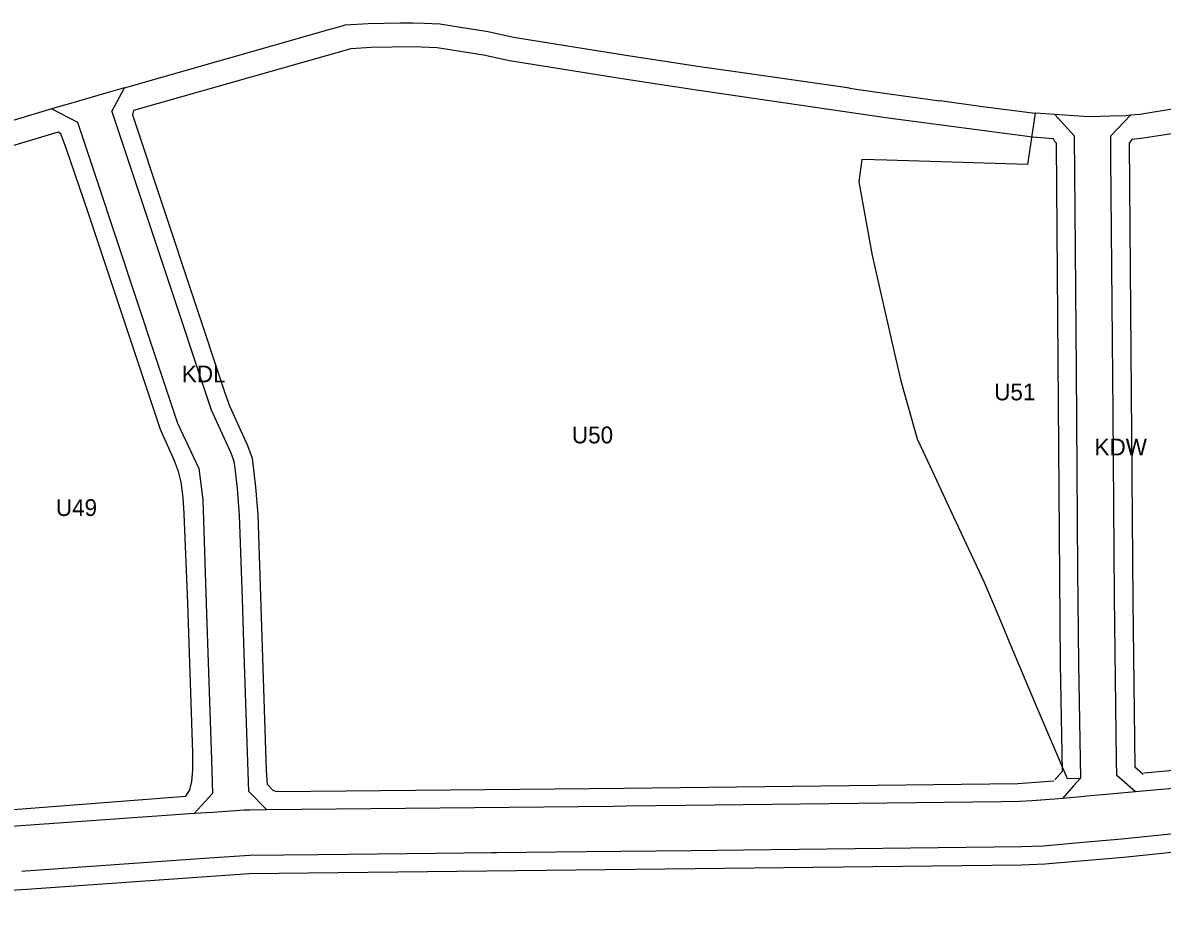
# Model space of a CAD drawing. Extents: x 7428080 to 7432143, y 5545880 to 5549217.
# Drawn here: x 7429638.6 to 7430015.1, y 5547123.1 to 5547416.2 of the extents above; entities that cross this region are included whole.
import ezdxf

# ---------------------------------------------------------------- set-up
doc = ezdxf.new("R2010")
doc.units = 0
for name, color, linetype in [('CZ_L_linie rozgraniczające tereny o różnym przeznaczeniu oraz różnych warunkach ich zabudowy i zagospodarowania', 7, 'Continuous'), ('CZ_L_maksymalne nieprzekraczalne linie zabudowy', 7, 'Continuous'), ('CZ_L_opisy_linie rozgraniczające tereny o różnym przeznaczeniu oraz różnych warunkach ich zabudowy i zagospodarowania', 7, 'Continuous')]:
    doc.layers.add(name, color=color, linetype=linetype)

msp = doc.modelspace()

# ---------------------------------------------------------------- linework, layer by layer
at = {"layer": 'CZ_L_linie rozgraniczające tereny o różnym przeznaczeniu oraz różnych warunkach ich zabudowy i zagospodarowania'}
for p, q in [((7429740.89, 5547414.25), (7429743.8, 5547415.09)), ((7429743.8, 5547415.09), (7429745.11, 5547415.46)), ((7429745.11, 5547415.46), (7429752.68, 5547415.97)), ((7429752.68, 5547415.97), (7429763.33, 5547416.12)), ((7429763.33, 5547416.12), (7429767.47, 5547416.17)), ((7429767.47, 5547416.17), (7429771.35, 5547416.03)), ((7429771.35, 5547416.03), (7429776.37, 5547415.86)), ((7429776.37, 5547415.86), (7429783.18, 5547414.68)), ((7429783.18, 5547414.68), (7429792.42, 5547413.31)), ((7429672.25, 5547394.63), (7429740.89, 5547414.25)), ((7429792.42, 5547413.31), (7429800.73, 5547411.46)), ((7429800.73, 5547411.46), (7429837.89, 5547405.52)), ((7429837.89, 5547405.52), (7429862.35, 5547401.77)), ((7429862.35, 5547401.77), (7429874.06, 5547400.11)), ((7429874.06, 5547400.11), (7429874.06, 5547400.07)), ((7429874.06, 5547400.07), (7429887.98, 5547398.04)), ((7429887.98, 5547398.04), (7429908.01, 5547395.18)), ((7429666.07, 5547392.86), (7429654.4, 5547389.52)), ((7429672.25, 5547394.63), (7429666.07, 5547392.86)), ((7429668.08, 5547387.08), (7429672.25, 5547394.63)), ((7429908.01, 5547395.18), (7429911.79, 5547394.64)), ((7429911.79, 5547394.64), (7429911.78, 5547394.6)), ((7429911.78, 5547394.6), (7429917.02, 5547393.83)), ((7429917.02, 5547393.83), (7429925.63, 5547392.57)), ((7429925.63, 5547392.57), (7429925.63, 5547392.55)), ((7429925.63, 5547392.55), (7429941.57, 5547390.39)), ((7429651.16, 5547388.59), (7429648.15, 5547387.7)), ((7429654.4, 5547389.52), (7429651.16, 5547388.59)), ((7429941.57, 5547390.39), (7429941.69, 5547390.5)), ((7429941.69, 5547390.5), (7429955.68, 5547388.51)), ((7429955.68, 5547388.51), (7429973.08, 5547386.29)), ((7429648.15, 5547387.7), (7429592.29, 5547370.97)), ((7429648.15, 5547387.7), (7429656.66, 5547383.36)), ((7429668.05, 5547387.01), (7429668.08, 5547387.08)), ((7429669.59, 5547382.48), (7429668.05, 5547387.01)), ((7429973.08, 5547386.29), (7429970.57, 5547369.31)), ((7429973.22, 5547386.27), (7429973.08, 5547386.29)), ((7429979.63, 5547385.82), (7429973.22, 5547386.27)), ((7429986.12, 5547378.67), (7429979.63, 5547385.82)), ((7429986.06, 5547385.37), (7429979.63, 5547385.82)), ((7429990.95, 5547385.03), (7429986.06, 5547385.37)), ((7429998.06, 5547385.28), (7429990.95, 5547385.03)), ((7430003.21, 5547385.45), (7429998.06, 5547385.28)), ((7429998.12, 5547378.78), (7430004.66, 5547385.59)), ((7430004.66, 5547385.59), (7430003.21, 5547385.45)), ((7430007.67, 5547385.89), (7430004.66, 5547385.59)), ((7430019.77, 5547387.83), (7430007.67, 5547385.89)), ((7429656.66, 5547383.36), (7429662.83, 5547364.76)), ((7429682.22, 5547344.39), (7429669.59, 5547382.48)), ((7429986.32, 5547354.32), (7429986.12, 5547378.67)), ((7429998.12, 5547378.77), (7429998.12, 5547378.78)), ((7429998.18, 5547371.61), (7429998.12, 5547378.77)), ((7429915.8, 5547370.97), (7429914.87, 5547363.59)), ((7429924.07, 5547370.72), (7429915.8, 5547370.97)), ((7429970.57, 5547369.31), (7429924.07, 5547370.72)), ((7429998.56, 5547323.45), (7429998.18, 5547371.61)), ((7429662.83, 5547364.76), (7429682.68, 5547304.92)), ((7429914.87, 5547363.59), (7429919.24, 5547339.24)), ((7429986.74, 5547301.21), (7429986.32, 5547354.32)), ((7429685.3, 5547335.12), (7429682.22, 5547344.39)), ((7429919.24, 5547339.24), (7429926.66, 5547306.82)), ((7429700.91, 5547288.06), (7429685.3, 5547335.12)), ((7429998.85, 5547287.15), (7429998.56, 5547323.45)), ((7429926.66, 5547306.82), (7429928.75, 5547297.78)), ((7429682.68, 5547304.92), (7429689.67, 5547283.83)), ((7429987.27, 5547235.34), (7429986.74, 5547301.21)), ((7429928.75, 5547297.78), (7429934.12, 5547278.69)), ((7429707.43, 5547273.94), (7429700.91, 5547288.06)), ((7429999.34, 5547226.25), (7429998.85, 5547287.15)), ((7429689.67, 5547283.83), (7429696.75, 5547268.86)), ((7429934.12, 5547278.69), (7429938.42, 5547269.48)), ((7429708.47, 5547271.19), (7429707.43, 5547273.94)), ((7429696.75, 5547268.86), (7429698.08, 5547258.5)), ((7429708.77, 5547268.92), (7429708.47, 5547271.19)), ((7429709.53, 5547262.07), (7429708.77, 5547268.92)), ((7429938.42, 5547269.48), (7429946.15, 5547252.89)), ((7429710.25, 5547253.37), (7429709.53, 5547262.07)), ((7429698.08, 5547258.5), (7429699.33, 5547220.75)), ((7429711.17, 5547225.79), (7429710.25, 5547253.37)), ((7429946.15, 5547252.89), (7429956.14, 5547231.51)), ((7429987.52, 5547204.3), (7429987.27, 5547235.34)), ((7429956.14, 5547231.51), (7429961.16, 5547219.77)), ((7429711.77, 5547207.61), (7429711.17, 5547225.79)), ((7430000.04, 5547172.25), (7429999.34, 5547226.25)), ((7429699.33, 5547220.75), (7429700.93, 5547172.52)), ((7429961.16, 5547219.77), (7429965.13, 5547210.25)), ((7429713.28, 5547162.06), (7429711.77, 5547207.61)), ((7429965.13, 5547210.25), (7429973.64, 5547189.8)), ((7429988.17, 5547166.5), (7429987.52, 5547204.3)), ((7429973.64, 5547189.8), (7429983.74, 5547166.4)), ((7429700.93, 5547172.52), (7429701.25, 5547161.39)), ((7430000.14, 5547167.35), (7430000.04, 5547172.25)), ((7429983.74, 5547166.4), (7429988.09, 5547166.41)), ((7429988.09, 5547166.41), (7429985.84, 5547163.89)), ((7429988.09, 5547166.41), (7429988.17, 5547166.5)), ((7430006.32, 5547161.92), (7430000.14, 5547167.35)), ((7429985.84, 5547163.89), (7429982.17, 5547159.77)), ((7430013.52, 5547162.58), (7430006.32, 5547161.92)), ((7430021.5, 5547163.32), (7430013.52, 5547162.58)), ((7429701.25, 5547161.39), (7429695.25, 5547154.73)), ((7429719.25, 5547155.99), (7429713.28, 5547162.06)), ((7429962.02, 5547158.64), (7429857.65, 5547157.42)), ((7429962.03, 5547158.64), (7429962.02, 5547158.64)), ((7429967.96, 5547158.71), (7429962.03, 5547158.64)), ((7429972.04, 5547159), (7429967.96, 5547158.71)), ((7429979.57, 5547159.54), (7429972.04, 5547159)), ((7429982.17, 5547159.77), (7429979.57, 5547159.54)), ((7429988.27, 5547160.32), (7429982.17, 5547159.77)), ((7429990.22, 5547160.49), (7429988.27, 5547160.32)), ((7429995.38, 5547160.95), (7429990.22, 5547160.49)), ((7430000.27, 5547161.38), (7429995.38, 5547160.95)), ((7430005.08, 5547161.8), (7430000.27, 5547161.38)), ((7430006.32, 5547161.92), (7430005.08, 5547161.8)), ((7429701.42, 5547155.17), (7429695.25, 5547154.73)), ((7429711.88, 5547155.91), (7429701.42, 5547155.17)), ((7429712.04, 5547155.89), (7429711.88, 5547155.91)), ((7429712.19, 5547155.92), (7429712.04, 5547155.89)), ((7429713.49, 5547155.93), (7429712.19, 5547155.92)), ((7429719.25, 5547155.99), (7429713.49, 5547155.93)), ((7429833.67, 5547157.14), (7429719.25, 5547155.99)), ((7429837.88, 5547157.19), (7429833.67, 5547157.14)), ((7429857.65, 5547157.42), (7429837.88, 5547157.19)), ((7429695.25, 5547154.73), (7429610.2, 5547148.7)), ((7430022.14, 5547148.34), (7430001.8, 5547146.27)), ((7429968.57, 5547143.72), (7429931.95, 5547143.29)), ((7429975.77, 5547144.03), (7429968.57, 5547143.72)), ((7429989.03, 5547145.24), (7429975.77, 5547144.03)), ((7430001.8, 5547146.27), (7429989.03, 5547145.24)), ((7429698.49, 5547139.92), (7429639.44, 5547135.68)), ((7429713.55, 5547140.88), (7429698.49, 5547139.92)), ((7429736.16, 5547141.16), (7429713.55, 5547140.88)), ((7429775.24, 5547141.56), (7429736.16, 5547141.16)), ((7429793.51, 5547141.75), (7429775.24, 5547141.56)), ((7429795.27, 5547141.77), (7429793.51, 5547141.75)), ((7429824.77, 5547142.08), (7429795.27, 5547141.77)), ((7429859.41, 5547142.44), (7429824.77, 5547142.08)), ((7429876.72, 5547142.65), (7429859.41, 5547142.44)), ((7429931.95, 5547143.29), (7429876.72, 5547142.65)), ((7429639.35, 5547135.73), (7429638.24, 5547135.65)), ((7429639.35, 5547135.72), (7429639.35, 5547135.73)), ((7429639.44, 5547135.68), (7429639.35, 5547135.72))]:
    msp.add_line(p, q, dxfattribs=at)
at = {"layer": 'CZ_L_maksymalne nieprzekraczalne linie zabudowy'}
for points in [[(7429979.61, 5547165.91), (7429982.13, 5547168.74), (7429981.52, 5547204.25), (7429980.14, 5547376.33), (7429979.6, 5547376.93), (7429979.16, 5547377.84), (7429972.23, 5547378.33), (7429924.52, 5547384.63), (7429861.21, 5547393.85), (7429836.68, 5547397.61), (7429799.44, 5547403.57), (7429790.87, 5547405.45), (7429775.51, 5547407.88), (7429767.55, 5547408.17), (7429753.67, 5547407.99), (7429746.96, 5547407.57), (7429675.13, 5547387.13), (7429674.82, 5547385.73), (7429705.22, 5547294.12), (7429706.85, 5547289.52), (7429712.88, 5547276.45), (7429714.38, 5547272.24), (7429715.5, 5547262.69), (7429716.25, 5547253.61), (7429719.05, 5547169.05), (7429719.32, 5547164.48), (7429721.22, 5547162.54), (7429722.35, 5547162.02), (7429837.27, 5547163.18), (7429967.39, 5547164.7), (7429979.27, 5547165.54)], [(7429612.64, 5547154.3), (7429692.42, 5547160.54), (7429693.74, 5547162.58), (7429694.48, 5547165.31), (7429694.8, 5547169.26), (7429694.8, 5547174.9), (7429693.17, 5547224.29), (7429691.96, 5547253.88), (7429691.6, 5547259.19), (7429690.96, 5547264.33), (7429690.05, 5547267.84), (7429688.75, 5547271.33), (7429684.07, 5547281.69), (7429660.19, 5547353.47), (7429653.08, 5547374.39), (7429651.19, 5547379.41), (7429650.23, 5547379.97), (7429574.15, 5547357.19)], [(7430021.09, 5547379.94), (7430008.92, 5547377.98), (7430005.12, 5547377.6), (7430004.16, 5547376.4), (7430005.36, 5547224.97), (7430006.08, 5547170.22), (7430008.78, 5547167.74)], [(7430009.06, 5547168.2), (7430021.11, 5547169.3), (7430040.61, 5547170.39), (7430056.08, 5547170.46), (7430083.44, 5547170.89), (7430108.98, 5547171.03), (7430134.51, 5547169.47), (7430176.45, 5547161.98), (7430197.83, 5547153.55), (7430221.84, 5547144.49)], [(7430206.1, 5547121.66), (7430183.43, 5547130.1), (7430168.99, 5547135.98), (7430123.79, 5547143.94), (7430120.43, 5547144.05), (7430087.76, 5547143.99), (7430040.61, 5547143.44), (7430023.55, 5547142.41), (7430002.37, 5547140.29), (7429976.31, 5547138.05), (7429968.64, 5547137.72), (7429713.38, 5547134.86), (7429639.87, 5547129.69), (7429607.51, 5547127.67)]]:
    msp.add_lwpolyline(points, dxfattribs=at)

# ---------------------------------------------------------------- texts
at = {"layer": 'CZ_L_opisy_linie rozgraniczające tereny o różnym przeznaczeniu oraz różnych warunkach ich zabudowy i zagospodarowania'}
for s, p in [('KDL', (7429691.16, 5547297.3)), ('U51', (7429959.58, 5547291.37)), ('U50', (7429820.04, 5547277.14)), ('KDW', (7429992.75, 5547273.15)), ('U49', (7429649.53, 5547253.14))]:
    msp.add_text(s, height=5.549, dxfattribs=at).set_placement(p)

doc.saveas('drawing.dxf')
